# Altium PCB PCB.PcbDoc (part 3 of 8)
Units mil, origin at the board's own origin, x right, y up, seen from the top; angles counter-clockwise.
Board outline 11229.24 x 7764.43 mil, 14 copper layers (Top Layer, GND1, Signal 1, GND2, Signal 2, GND3, Singal 3, Power 1, GND4, Power 2, GND5, Power 3, GND6, Bottom Layer), stack 91.892 mil thick; 877 components, 305 nets, 2660 pads, 2851 vias.
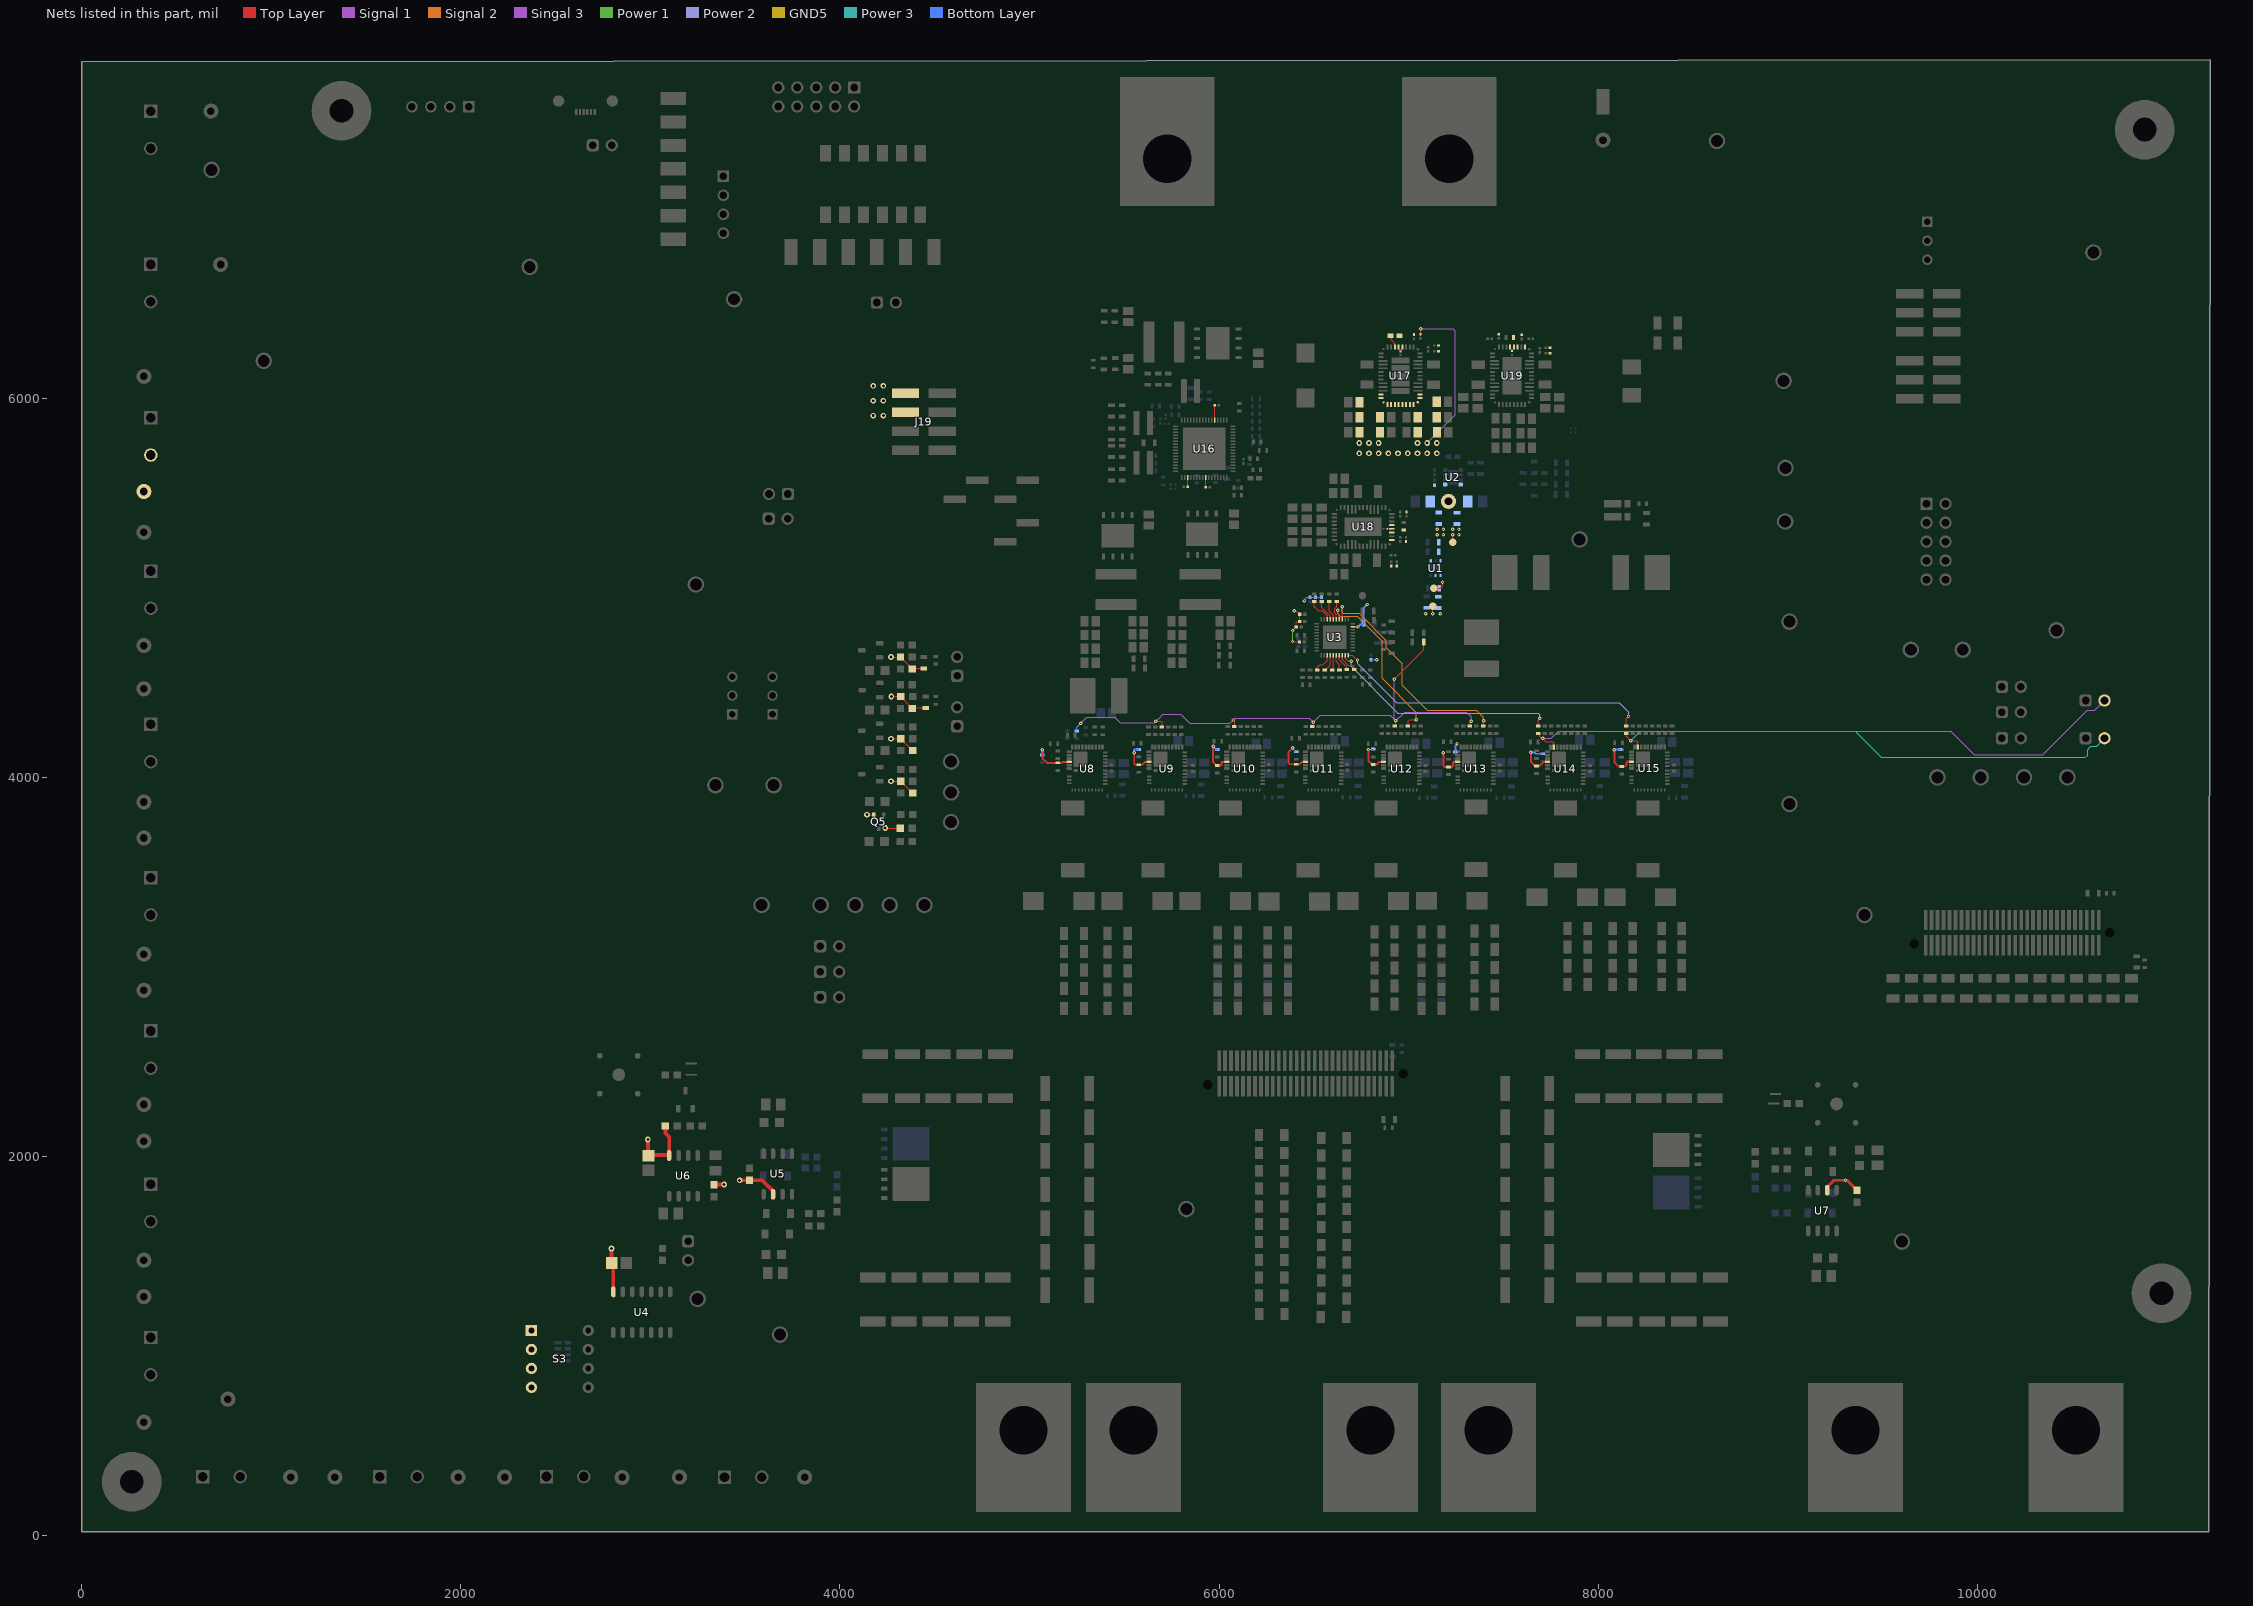
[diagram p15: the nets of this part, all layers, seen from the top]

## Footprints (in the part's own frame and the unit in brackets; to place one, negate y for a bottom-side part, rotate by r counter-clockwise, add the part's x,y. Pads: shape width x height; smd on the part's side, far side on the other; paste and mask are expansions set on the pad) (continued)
Samtec_TSM-103-01-x-DV [mm] "Header, 2.54mm, 3x2, SMT"
  rect 3.68x1.27 smd: 1(-2.475,2.54) 2(2.475,2.54) 3(-2.475,0) 4(2.475,0) 5(-2.475,-2.54) 6(2.475,-2.54)
  silkscreen extent -1.75,-3.81 1.65,3.9, body extent -3.85,-3.81 3.85,3.81, height 9.65
Samtec_TSM-104-01-x-DV [mm] "Header, 2.54mm, 4x2, SMT"
  rect 3.68x1.27 smd: 1(-2.475,3.81) 2(2.475,3.81) 3(-2.475,1.27) 4(2.475,1.27) 5(-2.475,-1.27) 6(2.475,-1.27) 7(-2.475,-3.81) 8(2.475,-3.81)
  silkscreen extent -1.65,-5.08 1.65,5.22, body extent -3.85,-5.08 3.85,5.08, height 9.65
SIL0008D_SMD [mm] "SIP, 8-Leads, Body 2.8x3.0mm, Pitch 0.65mm, Thermal Pad 1.9x1.1mm"
  rrect12% 1.04x0.85 on Bottom Paste: 0(0,-0.525) 0(0,0.525)
  rrect40% 0.6x0.5 smd paste-0.05 mask-0.05: 1(-1.05,0.975) 2(-1.05,0.325) 3(-1.05,-0.325) 4(-1.05,-0.975) 5(1.05,-0.975) 6(1.05,-0.325) 7(1.05,0.325) 8(1.05,0.975)
  rrect17% 1.2x2 smd paste-0.6 mask-0.05: 9(0,0)
  silkscreen extent -1.53,-1.63 1.53,1.63, body extent -1.4,-1.5 1.4,1.5, height 1.53
SLR1050 [mm] "SMD, 2-Leads, Body 10.2x7mm"
  rect 2x3.1 smd: 1(-4.175,0) 2(4.175,0)
  silkscreen extent -4.7,-3.5 4.7,3.5, body extent -4.8,-3.5 4.8,3.5, height 4.95
SOD-123 [mm] "On Semi recommended land pattern"
  rect 0.915x1.22 smd: 1(-1.637,0) 2(1.637,0)
  silkscreen extent -2.74,-1.17 2.03,1.17, body extent -1.93,-0.9 1.93,0.9, height 1.35
SOT-23 [mm] "SOT23, 3-Leads, Body 2.9x1.3mm, Pitch 0.95mm, Lead Span 2.5mm, IPC Medium Density"
  rrect50% 1x0.6 smd: 1(-1.2,0.95) 2(-1.2,-0.95) 3(1.2,0)
  silkscreen extent -1.63,-1.5 0.7,1.5, body extent -1.16,-1.45 1.21,1.45, height 1
SOT-323 [mm] "Diodes Inc recommended land pattern.  2016-02-24"
  rrect21% 0.6x0.47 smd: 1(-0.95,0.65) 2(-0.95,-0.65) 3(0.95,0)
  silkscreen extent -1.14,-1.22 0.78,1.22, body extent -1.13,-1.13 1.12,1.12, height 1.13
SW_78B04ST [mil] "Switch, DIP Slide, 4Pos"
  rect 60x60 hole 31: 1(-150,150)
  round 60 hole 31: 2(-150,50) 3(-150,-50) 4(-150,-150) 5(150,-150) 6(150,-50) 7(150,50) 8(150,150)
  silkscreen extent -174,213 -160,227, body extent -195,-245 195,245, height 337
SW_EG1218 [mm] "TH, 3-Leads, Body 4x11.6mm, Pitch 2.5mm"
  rect 1.4x1.4 hole 0.9: 1(-2.5,0)
  round 1.4 hole 0.9: 2(0,0) 3(2.5,0)
  silkscreen extent -5.8,-2 5.8,2.3, body extent -5.8,-2 5.8,2, height 7.4
SW_SDA06H1SBD [mil] "Swittch SPST 6 Pos."
  rrect7% 59x85 smd: 1(-250,-162) 2(-150,-162) 3(-50,-162) 4(50,-162) 5(150,-162) 6(250,-162) 7(250,162) 8(150,162) 9(50,162) 10(-50,162) 11(-150,162) 12(-250,162)
  body extent -340,-150 340,150, height 197
TC164 [mm] "SMD, 8-Leads, Body 3.2x1.6mm, Pitch 0.8mm"
  rect 0.9x0.45 smd: 1(-0.65,1.2) 2(-0.65,0.4) 3(-0.65,-0.4) 4(-0.65,-1.2) 5(0.65,-1.2) 6(0.65,-0.4) 7(0.65,0.4) 8(0.65,1.2)
  silkscreen extent -1.5,-1.9 1.5,1.9, body extent -0.87,-1.68 0.87,1.68, height 0.71
Testpoint_Keystone_Miniature [mil] "Miniature SMT test point"
  rect 135x70 smd: 1(0,0)
  silkscreen extent -78,-46 78,45, body extent -52,-20 52,20, height 61
TI_Stacked_Overlay_Small [mil]
  silkscreen extent -418,-98 418,98
TP_SM_1MM [mm] "1mm Test Point, SMT"
  round 1 smd paste-0.5: 1(0,0)
TSW-102-07-G-S [mm] "Samtec 100mil, 1x2, 230 mil above insulator"
  rrect50% 1.65x1.65 hole 1.016: 1(-1.27,0)
  round 1.65 hole 1.016: 2(1.27,0)
  silkscreen extent -3.17,-1.27 2.54,1.27, body extent -2.54,-1.27 2.54,1.27, height 8.38
WEEE_Minimum [mil] "WEEElie bin"
  silkscreen extent -95,-172 99,104
Wurth_61000218321 [mm] "Header, 2.54mm, 2x1, SMT"
  rect 1x3 smd: 1(-1.27,1.5) 2(1.27,-1.5)
  silkscreen extent -2.86,-1.27 2.54,1.27, body extent -2.54,-2.5 2.54,2.5, height 6.3
XEL6030_320 [mm] "SMD, 2-Leads, Body 66.36x6.56 mm"
  rrect7% 1.43x5.5 smd: 1(-2.02,0) 2(2.02,0)
  body extent -3.28,-3.38 3.28,3.38, height 3.2

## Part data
C1 C3: library part CMP-0007507-5, "CAP, CERM, 10 uF, 25 V, +/- 20%, X5R, 0603", Cap_Case=0603, Manufacturer="Taiyo Yuden", TempCo=X5R, Tolerance_%=20%, Value1=Unknown, Value2=25V, ValueDisplayed=10uF
C2: library part CMP-0006802-4, "CAP, CERM, 0.1 uF, 50 V, +/- 10%, X7R, 0603", Cap_Case=0603, Manufacturer=AVX, Supplier Part Number 1=478-5052-1-ND, TempCo=X7R, Tolerance_%=10%, Value1=Unknown, Value2=50V, ValueDisplayed=0.1uF
C4: library part CMP-0007007-5, "CAP, CERM, 10 uF, 25 V, +/- 20%, X5R, 0603", Cap_Case=0603, Manufacturer=TDK, Supplier Part Number 1=445-9015-1-ND, TempCo=X5R, Tolerance_%=20%, Value1="0.004639 ohm", Value2=25V, ValueDisplayed=10uF
C5 C6 C299 C307 C317: library part CMP-0008305-2, "CAP, CERM, 22 uF, 25 V, +/- 20%, X5R, 0805", Cap_Case=0805, Manufacturer=MuRata, Supplier Part Number 1=490-10749-1-ND, TempCo=X5R, Tolerance_%=20%, Value1=Unknown, Value2=25V, ValueDisplayed=22uF
C7 C16 C19 C20 C25 C27 C30: library part CMP-0007136-5, "CAP, CERM, 1 uF, 16 V, +/- 10%, X7R, AEC-Q200 Grade 1, 0603", Cap_Case=0603, Manufacturer=MuRata, Supplier Part Number 1=490-5241-6-ND, TempCo=X7R, Tolerance_%=10%, Value1=Unknown, Value2=16V, ValueDisplayed=1uF
C8: library part CMP-0006319-2, "CAP, CERM, 3300 pF, 50 V, +/- 10%, X7R, AEC-Q200 Grade 1, 0402", Cap_Case=0402, Manufacturer=TDK, Supplier Part Number 1=445-6891-1-ND, TempCo=X7R, Tolerance_%=10%, Value1="0.785178 ohm", Value2=50V, ValueDisplayed=3300pF
C9: library part CMP-0006949-5, "CAP, CERM, 4.7 uF, 10 V, +/- 10%, X5R, 0603", Cap_Case=0603, Manufacturer=Kemet, Supplier Part Number 1=399-5503-1-ND, TempCo=X5R, Tolerance_%=10%, Value1="0.006 ohm", Value2=10V, ValueDisplayed=4.7uF
C10 C12: library part CMP-0006233-2, "CAP, CERM, 100 pF, 25 V, +/- 5%, C0G/NP0, 0402", Cap_Case=0402, Manufacturer=Kemet, Supplier Part Number 1=399-1022-1-ND, TempCo=C0G/NP0, Tolerance_%=5%, Value1=Unknown, Value2=25V, ValueDisplayed=100pF
C11 C13 C14 C15: library part CMP-0006439-2, "CAP, CERM, 22 pF, 50 V, +/- 5%, C0G/NP0, 0402", Cap_Case=0402, Manufacturer=MuRata, Supplier Part Number 1=81-GRM1555C1H220JA1D, TempCo=C0G/NP0, Tolerance_%=5%, Value1=Unknown, Value2=50V, ValueDisplayed=22pF
C17 C18: library part CMP-0006235-2, "CAP, CERM, 1000 pF, 50 V, +/- 10%, X7R, 0402", Cap_Case=0402, Manufacturer=Kemet, Supplier Part Number 1=399-1032-1-ND, TempCo=X7R, Tolerance_%=10%, Value1=Unknown, Value2=50V, ValueDisplayed=1000pF
C21 C22: library part CMP-0006663-2, "CAP, CERM, 2200 pF, 25 V, +/- 10%, X7R, 0402", Cap_Case=0402, Manufacturer=MuRata, Supplier Part Number 1=490-5419-1-ND, TempCo=X7R, Tolerance_%=10%, Value1=Unknown, Value2=25V, ValueDisplayed=2200pF
C23 C24: library part CMP-0064970-1, "CAP, CERM, 0.1 uF, 16 V,+/- 10%, X7R, 0201", Cap_Case=0201, Manufacturer=MuRata, Supplier Part Number 1=81-GRM033Z71C104KE4D, TempCo=X7R, Tolerance_%=10%, Value1=Unknown, Value2=16V, ValueDisplayed=0.1uF
C26 C31: library part CMP-0007567-2, "CAP, CERM, 0.1 uF, 25 V, +/- 10%, X7R, 0805", Cap_Case=0805, Manufacturer=AVX, Supplier Part Number 1=478-3755-1-ND, TempCo=X7R, Tolerance_%=10%, Value1="0.28 ohm", Value2=25V, ValueDisplayed=0.1uF
C28 C29: library part CMP-0007542-2, "CAP, CERM, 0.01 uF, 100 V, +/- 5%, X7R, 0805", Cap_Case=0805, Manufacturer=AVX, Supplier Part Number 1=478-3745-1-ND, TempCo=X7R, Tolerance_%=5%, Value1="0.078 ohm", Value2=100V, ValueDisplayed=0.01uF
C32 C33 C34 C35 C36 C37 C38 C39 C40 C41 C42 C43 C44 C45 C46 C47 C48 C49 C50 C51 C52 C53 C54 C55 C56 C57 C58 C59 C60 C61 C62 C63 C64 C65 C66 C67 C68 C69 C70 C71 C72 C73 C74 C75 C76 C77 C78 C79 C80 C81 C89 C90 C91 C92 C93 C94 C95 C96 C97 C98 C99 C100 C101 C102 C103 C104 C105 C106 C107 C108 C109 C110 C111 C112 C113 C114 C115 C116 C117 C118 C119 C120 C121 C122 C123 C124 C125 C126 C127 C128 C129 C130 C131 C132 C133 C134 C135 C136 C137 C138 C139 C140 C141 C142 C143 C144 C145 C146 C147 C148 C149 C150 C151 C152 C153 C154 C155 C156 C157 C158 C159 C160 C161 C162 C163 C164 C165 C166 C167 C168 C169 C170 C173 C174 C175 C176 C189 C190 C191 C192 C205 C206 C207 C208 C221 C222 C223 C224 C237 C238 C239 C240 C253 C254 C255 C256 C269 C270 C271 C272 C285 C286 C287 C288: library part CMP-0008932-2, "CAP, CERM, 220 uF, 4 V, +/- 20%, X5R, 1206_190", Cap_Case=1206, Manufacturer=MuRata, Supplier Part Number 1=490-9774-1-ND, TempCo=X5R, Tolerance_%=20%, Value1=Unknown, Value2=4V, ValueDisplayed=220uF
C82: library part CMP-0006810-4, "CAP, CERM, 0.082 uF, 16 V, +/- 10%, X7R, 0603", Cap_Case=0603, Manufacturer=AVX, Supplier Part Number 1=478-1238-1-ND, TempCo=X7R, Tolerance_%=10%, Value1="0.042 ohm", Value2=16V, ValueDisplayed=0.082uF
C83 C84 C85 C86: library part CMP-0092821-1, "220µF Molded Tantalum Polymer Capacitor 25V 2924 (7361 Metric) 100mOhm @ 100kHz", Digikey Part Number=478-12518-1-ND, Leakage Current=550uA, Manufacturer=AVX, Mouser Part Number=581-TCN4227M025R0100, Operating Temperature Range="-55°C to +105°C", Tolerance_%=20%, ValueDisplayed=220uF
C87 C88: library part CMP-0008667-2, "CAP, CERM, 22 uF, 35 V, +/- 20%, X5R, 1206", Cap_Case=1206_180, Manufacturer=TDK, Supplier Part Number 1=445-8045-1-ND, TempCo=X5R, Tolerance_%=20%, Value1="0.002398 ohm", Value2=35V, ValueDisplayed=22uF
C171 C187 C203 C219 C235 C251 C267 C283: library part CMP-0006673-2, "CAP, CERM, 1000 pF, 50 V, +/- 10%, X7R, 0402", Cap_Case=0402, Manufacturer=MuRata, Supplier Part Number 1=490-1303-1-ND, TempCo=X7R, Tolerance_%=10%, Value1=Unknown, Value2=50V, ValueDisplayed=1000pF
C172 C177 C188 C193 C204 C209 C220 C225 C236 C241 C252 C257 C268 C273 C284 C289: library part CMP-0012242-3, "CAP, Aluminum Polymer, 470 uF, 2.5 V, +/- 20%, 0.003 ohm, SMD_7.3x1.9x4.3mm SMD", Manufacturer=Panasonic, Supplier Part Number 1=95W5408, Tolerance_%=20%, Value1="0.003 ohm", Value2=2.5V, ValueDisplayed=470uF
C178 C194 C210 C226 C242 C258 C274 C290: library part CMP-0086485-1, "CAP CER 1UF 25V X6S 0402", Manufacturer=Murata, TempCo=22%, Tolerance_%=10%
C179 C180 C181 C195 C196 C197 C211 C212 C213 C227 C228 C229 C243 C244 C245 C259 C260 C261 C275 C276 C277 C291 C292 C293: library part CMP-0008293-2, "CAP, CERM, 22 uF, 16 V, +/- 20%, X5R, 0805", Cap_Case=0805, Manufacturer=MuRata, PartNumber=GRM21BR61C226ME44, TempCo=X5R, Tolerance_%=20%, Value1=Unknown, Value2=16V, ValueDisplayed=22uF
C182 C186 C199 C202 C216 C218 C230 C234 C248 C250 C264 C266 C278 C282 C295 C298: library part CMP-0006356-2, "CAP, CERM, 0.1 uF, 50 V, +/- 10%, X7R, AEC-Q200 Grade 1, 0402", Cap_Case=0402, Manufacturer=MuRata, Supplier Part Number 1=490-10672-1-ND, TempCo=X7R, Tolerance_%=10%, Value1=Unknown, Value2=50V, ValueDisplayed=0.1uF
C183 C184 C198 C200 C214 C215 C231 C232 C246 C247 C262 C263 C280 C281 C294 C296: library part CMP-0006263-2, "CAP, CERM, 2.2 uF, 10 V, +/- 10%, X5R, 0402", Cap_Case=0402, Manufacturer=TDK, PartNumber=C1005X5R1A225K050BC, Supplier Part Number 1=445-7392-1-ND, TempCo=X5R, Tolerance_%=10%, Value1=Unknown, Value2=10V, ValueDisplayed=2.2uF
C185 C201 C217 C233 C249 C265 C279 C297: library part CMP-0006233-2, "CAP, CERM, 100 pF, 25 V, +/- 5%, C0G/NP0, 0402", Cap_Case=0402, Manufacturer=Kemet, PartNumber=C0402C101J3GACTU, Supplier Part Number 1=399-1022-1-ND, TempCo=C0G/NP0, Tolerance_%=5%, Value1=Unknown, Value2=25V, ValueDisplayed=100pF
C300 C308 C318 C346 C347 C352: library part CMP-0009719-2, "CAP, CERM, 0.1 uF, 25 V, +/- 10%, X5R, 0201", Cap_Case=0201, Manufacturer=MuRata, Supplier Part Number 1=GRM033R61E104KE14D-ND, TempCo=X5R, Tolerance_%=10%, Value1=Unknown, Value2=25V, ValueDisplayed=0.1uF
C301 C302 C303 C306 C309 C310 C311 C312 C313 C316 C359 C360 C361 C362 C363 C364 C365 C366 C367 C368 C372 C373 C374 C375 C376 C377 C378 C379 C380 C381 C385 C386 C387 C388 C390 C391 C392 C393 C394 C395 C398 C399 C400: library part CMP-0008280-2, "CAP, CERM, 100 uF, 6.3 V, +/- 20%, X5R, 0805", Cap_Case=0805, Manufacturer=MuRata, TempCo=X5R, Tolerance_%=20%, Value1=Unknown, Value2=6.3V, ValueDisplayed=100uF
C304 C305 C314 C319 C322 C323 C324 C326 C327 C328 C331 C332 C333 C334 C335 C396: library part CMP-0007324-5, "CAP, CERM, 22 uF, 10 V, +/- 20%, X5R, 0603", Cap_Case=0603, Manufacturer=MuRata, Supplier Part Number 1=490-10476-1-ND, TempCo=X5R, Tolerance_%=20%, Value1=Unknown, Value2=10V, ValueDisplayed=22uF
C315 C330 C339 C340 C341 C401: library part CMP-0086193-1, "CAP, CERM, 10 µF, 10 V,+/- 10%, X5R, 0603", Cap_Case=0603, Manufacturer=MuRata, TempCo=X5R, Tolerance_%=10%, Value2=10V, ValueDisplayed=10µF
C320 C321: library part CMP-0078699-1, "CAP, CERM, 47 µF, 10 V,+/- 20%, X5R, 0805", Cap_Case=0805, Manufacturer=MuRata, Supplier Part Number 1=490-9961-1-ND, TempCo=X5R, Tolerance_%=20%, Value2=10V, ValueDisplayed=47µF
C325: library part CMP-0006581-2, "CAP, CERM, 4.7 uF, 10 V, +/- 20%, X5R, 0402", Cap_Case=0402, Manufacturer=MuRata, TempCo=X5R, Tolerance_%=20%, Value1=Unknown, Value2=10V, ValueDisplayed=4.7uF
C329: library part CMP-0007313-5, "CAP, CERM, 47 uF, 6.3 V, +/- 20%, X5R, 0603", Cap_Case=0603, Manufacturer=MuRata, TempCo=X5R, Tolerance_%=20%, Value1=Unknown, Value2=6.3V, ValueDisplayed=47uF
C336: library part CMP-0011853-2, "CAP, TA, 47 uF, 35 V, +/- 20%, 0.9 ohm, AEC-Q200 Grade 1, SMD", Cap_Case=7343-43, Manufacturer=AVX, Supplier Part Number 1=478-3958-1-ND, Tolerance_%=20%, Value1="0.9 ohm", Value2=35V, ValueDisplayed=47uF
C337 C338: library part CMP-0006543-2, "CAP, CERM, 2.2 uF, 6.3 V, +/- 10%, X5R, 0402", Cap_Case=0402, Manufacturer=MuRata, Supplier Part Number 1=81-GRM155R60J225KE5D, TempCo=X5R, Tolerance_%=10%, Value1=Unknown, Value2=6.3V, ValueDisplayed=2.2uF
C342: library part CMP-0006268-1, "CAP, CERM, 4.7 uF, 10 V, +/- 10%, X5R, 0402", Cap_Case=0402_065, Manufacturer=TDK, Supplier Part Number 1=445-13820-1-ND, TempCo=X5R, Tolerance_%=10%, Value1="0.003417 ohm", Value2=10V, ValueDisplayed=4.7uF
C343 C344: library part CMP-0064909-1, "CAP, CERM, 1 uF, 10 V,+/- 20%, X5R, 0201", Cap_Case=0201, Manufacturer=MuRata, Supplier Part Number 1=490-13226-1-ND, TempCo=X5R, Tolerance_%=20%, Value1=Unknown, Value2=10V, ValueDisplayed=1uF
C345 C397: library part CMP-0006545-1, "CAP, CERM, 22 uF, 6.3 V, +/- 20%, X5R, 0402", Cap_Case=0402, Manufacturer=MuRata, TempCo=X5R, Tolerance_%=20%, Value1=Unknown, Value2=6.3V, ValueDisplayed=22uF
C348 C349: library part CMP-0006620-2, "CAP, CERM, 1 uF, 35 V, +/- 20%, X5R, 0402", Cap_Case=0402, Manufacturer=MuRata, Supplier Part Number 1=490-10020-1-ND, TempCo=X5R, Tolerance_%=20%, Value1=Unknown, Value2=35V, ValueDisplayed=1uF
C350 C351: library part CMP-0006269-2, "CAP, CERM, 4.7 uF, 10 V, +/- 20%, X5R, 0402", Cap_Case=0402, Manufacturer=TDK, Supplier Part Number 1=445-8023-1-ND, TempCo=X5R, Tolerance_%=20%, Value1=Unknown, Value2=10V, ValueDisplayed=4.7uF
C353 C354 C355: library part CMP-0006553-3, "CAP, CERM, 4.7 uF, 6.3 V, +/- 20%, X5R, 0402", Cap_Case=0402, Manufacturer=MuRata, Supplier Part Number 1=490-5408-1-ND, TempCo=X5R, Tolerance_%=20%, Value1="0.009 ohm", Value2=6.3V, ValueDisplayed=4.7uF
C356: library part CMP-0086192-1, "CAP, CERM, 0.1 µF, 16 V,+/- 10%, X5R, 0201", Cap_Case=0201, Manufacturer=MuRata, TempCo=X5R, Tolerance_%=10%, Value2=16V, ValueDisplayed=0.1µF
C357 C358: library part CMP-0008656-2, "CAP, CERM, 47 uF, 25 V, +/- 20%, X5R, 1206_190", Cap_Case=1206, Manufacturer=TDK, PartNumber=C3216X5R1E476M160AC, Supplier Part Number 1=445-8047-1-ND, TempCo=X5R, Tolerance_%=20%, Value1=Unknown, Value2=25V, ValueDisplayed=47uF
C369 C382 C389: library part CMP-0006612-2, "CAP, CERM, 4.7 uF, 25 V, +/- 20%, X5R, 0402", Cap_Case=0402, Manufacturer=MuRata, TempCo=X5R, Tolerance_%=20%, Value1=Unknown, Value2=25V, ValueDisplayed=4.7uF
C370 C371 C383 C384: library part CMP-0008646-2, "CAP, CERM, 47 uF, 25 V, +/- 20%, JB, 1206", Cap_Case=1206, Manufacturer=TDK, Supplier Part Number 1=445-11717-1-ND, TempCo=JB, Tolerance_%=20%, Value1=Unknown, Value2=25V, ValueDisplayed=47uF
D1 D2 D4 D5 D8 D9 D11 D12: library part CMP-0028525-2, "Diode, Schottky, 30 V, 0.5 A, SOD-123", Manufacturer="ON Semiconductor", Value1=0.5A, Value2=0.43V
D3 D6 D10 D13 D18: library part CMP-0002829-3, "LED, Red, SMD", Color=red, Manufacturer=Lite-On, Value1=W, Value2=2V
D7: library part CMP-0028451-2, "Diode, Schottky, 30 V, 0.2 A, SOT-23", Manufacturer="Diodes Inc.", Value1=0.2A, Value2=0.65V
D14 D15 D16 D17: library part CMP-0002888-2, "LED, Green, SMD", Color=Green, Manufacturer=Lite-On, Value1=W, Value2=2V
H1 H3 H5 H7: library part CMP-0003617-1, "Machine Screw, Round, #4-40 x 1/4, Nylon, Philips panhead", Manufacturer="B&F Fastener Supply", Supplier Part Number 1=H542-ND
H2 H4 H6 H8: library part CMP-0003610-1, "Standoff, Hex, 0.5\"L #4-40 Nylon", Manufacturer=Keystone, Supplier Part Number 1=36-1902C-ND
J1 J4: library part CMP-0055331-1, "Header, 2.54mm, 4x1, Tin, TH", Color=Black, Current_A=4A, Manufacturer=Molex, Supplier Part Number 1=WM50016-04-ND, Voltage_V=250V
J2 J3 J5 J6 J8 J24 J29 J32 J38 J39 J40 J41 J42 J43 J44: library part CMP-0075405-3, "Header, 100mil, 2x1, Gold, TH", Color=Black, Current_A=6.3A, Manufacturer=Samtec, Supplier Part Number 1=SAM1029-02-ND, Voltage_V=550V
J7: library part CMP-0054834-2, "Header (shrouded), 100mil, 5x2, Gold, TH", Manufacturer="TE Connectivity", Supplier Part Number 1=A33159-ND
J9 J10: library part CMP-0003859-2, "C2000 controlCARD-180HSEC (60-pin addon) connector, SMT", Manufacturer=Samtec
J11 J12: library part CMP-0075154-1, "Connector, SMT, SMB Jack Assembly 50 ohm", Manufacturer="Cinch Connectivity", Supplier Part Number 1=J816-ND
J13 J14 J15 J16 J17 J18 J30 J31 J33 J34 J35 J36 J37: library part CMP-0055506-1, "Terminal Block, 2x1, 5mm, Green, TH", Color=Green, Manufacturer="Phoenix Contact", Supplier Part Number 1=277-6405-ND
J19: library part CMP-0075593-2, "Header, 2.54mm, 4x2, Gold, SMT", Color=Black, Current_A=4.9A, Manufacturer=Samtec, Supplier Part Number 1=TSM-104-01-L-DV-ND, Voltage_V=475V
J20 J21 J22: library part CMP-0054787-1, "Header, 2.54mm, 2x1, Gold, SMT", Color=Black, Manufacturer="Wurth Elektronik"
J23: library part CMP-0055367-1, "FFC/FPC Connector, 6 POS, 0.5mm, R/A, Tin, SMT", Color=withe,black, Current_A=5dA, Manufacturer=Molex, Supplier Part Number 1=WM11020CT-ND, Voltage_V=50V
J25 J27: library part CMP-0075648-2, "Header, 2.54mm, 3x2, Gold, SMT", Color=Black, Current_A=4.9A, Manufacturer=Samtec, Supplier Part Number 1=TSM-103-01-L-DV-ND, Voltage_V=475V
J26: "Header (shrouded), 100mil, 5x2, High-Temperature, Gold, TH", Manufacturer=3M, PartNumber=N2510-6002-RB, Supplier Part Number 1=MHC10K-ND
J28: library part CMP-0075048-1, "Header, 2.54mm, 3x1, Gold, TH", Manufacturer="Fischer Elektronik"
L1: library part CMP-0092884-1, "Fixed Ind 55NH 35A 0.2 Mohm SMD", Digikey Part Number=553-PA4059.550HLTCT-ND, Manufacturer=Pulse, Mouser Part Number=673-PA4059.550HLT, Operating Temperature Range="-40°C to +125°C", Test Frequency=100kHz, Tolerance_%=20%
L2 L3 L4 L5 L6 L7 L8 L9: library part CMP-0060908-1, "Inductor, Shielded, Ferrite, 150 nH, 51 A, 0.0004 ohm, SMD", Manufacturer=Coilcraft, Supplier Part Number 1=994-SLR1050A-151KEB, Value1="0.0004 ohm", Value2=51A, ValueDisplayed=150nH
L10 L11 L12: library part CMP-0061103-3, "Inductor, Shielded, Composite, 470 nH, 22.3 A, 0.00331 ohm, AEC-Q200 Grade 1, SMD", Manufacturer=Coilcraft, Value1="0.00331 ohm", Value2=22.3A, ValueDisplayed=470nH
L13 L14 L15: library part CMP-0087112-1, "Shielded Power Inductors", Manufacturer=Coilcraft
Logo1: library part CMP-0074844-1
Logo2: library part CMP-0074838-1, "Texas Instrument Corporate Signature"
Logo3: library part CMP-0074847-1, "FCC_disclaimer"
Logo4: library part CMP-0074769-1
NT1 NT2 NT3 NT4 NT5 NT6 NT7 NT8 NT9 NT10 NT11 NT12 NT13 NT14 NT15 NT16 NT17 NT18 NT19: library part CMP-0078142-4, "Single point connection between nets.", Manufacturer=N/A
Q1 Q2 Q3 Q4: library part CMP-0000556-1, "MOSFET, N-CH, 30 V, 100 A, DQH0008A (VSON-CLIP-8)", Alternate Manufacturer=None, Manufacturer="Texas Instruments", Supplier Part Number 1=296-27232-1-ND, Value1=0, Value2="18 nC"
Q5: library part CMP-0000010-3, "MOSFET, P-CH, -20 V, -0.39 A, SOT-323", Alternate Manufacturer=None, Manufacturer="Infineon Technologies", Value1=1
Q6 Q7 Q8 Q9: library part CMP-0000947-2, "MOSFET, N-CH, 100 V, 0.17 A, SOT-23", Alternate Manufacturer=None, Manufacturer="Fairchild Semiconductor", Supplier Part Number 1=BSS123NCT-ND, Value1=1, Value2="1.8 nC"
Q10 Q11 Q12: library part CMP-0000278-2, "MOSFET, 2-CH, N-CH, 25 V, 50 A, DQY0008A (LSON-CLIP-8)", Alternate Manufacturer=None, Manufacturer="Texas Instruments", Supplier Part Number 1=296-35026-1-ND, Value1=0.004, Value2="9.7 nC"
R1 R2 R5: library part CMP-0022900-4, "RES, 1.00, 1%, 0.1 W, 0603", Manufacturer=Yageo, Power_W=100mW, Supplier Part Number 1=311-1.00HRCT-ND, TempCo="200 ppm/C", Tolerance_%=1%, Value2=0.1W, Value_Code=1R00, ValueDisplayed=1.00
R3: library part CMP-0027760-1, "RES, 523 k, 1%, 0.05 W, 0201", Manufacturer="Yageo America", Power_W=50mW, Supplier Part Number 1=YAG2716CT-ND, TempCo="200 ppm/C", Tolerance_%=1%, Value2=0.05W, Value_Code=523k
R4 R8 R10 R15 R16 R17 R24 R25 R26 R27 R28 R29 R38 R139 R140 R141 R142 R143 R145 R146: library part CMP-0025697-4, "RES, 0, 5%, 0.1 W, AEC-Q200 Grade 0, 0603", Manufacturer=Vishay-Dale, Power_W=100mW, Supplier Part Number 1=541-0.0GCT-ND, TempCo="200 ppm/C", Tolerance_%=5%, Value2=0.1W, Value_Code=0000, ValueDisplayed=0
R6: library part CMP-0027261-3, "RES, 100 k, 1%, 0.05 W, 0201", Manufacturer=Vishay-Dale, Power_W=50mW, Supplier Part Number 1=541-100KAABCT-ND, TempCo="100 ppm/C", Tolerance_%=1%, Value2=0.05W, Value_Code=100k
R7 R9 R11 R12 R20 R21 R148 R150 R151 R153 R154 R156 R158 R160 R161 R162 R164 R166 R168 R169 R170 R172 R174 R175 R177 R178 R180 R182 R184 R185 R186 R188 R190 R192 R193 R194 R196 R198 R199 R201 R202 R204 R206 R208 R209 R210 R214: library part CMP-0026822-3, "RES, 0, 5%, 0.063 W, AEC-Q200 Grade 0, 0402", Manufacturer=Vishay-Dale, Power_W=63mW, Supplier Part Number 1=541-0.0JCT-ND, TempCo="200 ppm/C", Tolerance_%=5%, Value2=0.063W, Value_Code=0000, ValueDisplayed=0
R13: library part CMP-0022204-4, "RES, 20.0 k, 1%, 0.1 W, AEC-Q200 Grade 0, 0603", Manufacturer=Vishay-Dale, Power_W=100mW, Supplier Part Number 1=541-20.0KHCT-ND, TempCo="100 ppm/C", Tolerance_%=1%, Value2=0.1W, Value_Code=20k0, ValueDisplayed=20.0k
R14: library part CMP-0022150-4, "RES, 1.30 M, 1%, 0.1 W, AEC-Q200 Grade 0, 0603", Manufacturer=Vishay-Dale, Power_W=100mW, Supplier Part Number 1=541-1.30MHCT-ND, TempCo="100 ppm/C", Tolerance_%=1%, Value2=0.1W, Value_Code=1M30, ValueDisplayed=1.30M
R18: library part CMP-0026461-2, "RES, 59.0 k, 1%, 0.063 W, AEC-Q200 Grade 0, 0402", Manufacturer=Vishay-Dale, Power_W=63mW, Supplier Part Number 1=541-59.0KLCT-ND, TempCo="100 ppm/C", Tolerance_%=1%, Value2=0.063W, Value_Code=59k0, ValueDisplayed=59.0k
R19: library part CMP-0026875-3, "RES, 20 k, 5%, 0.063 W, AEC-Q200 Grade 0, 0402", Manufacturer=Vishay-Dale, Power_W=63mW, Supplier Part Number 1=541-20KJCT-ND, TempCo="200 ppm/C", Tolerance_%=5%, Value2=0.063W, Value_Code=20k0, ValueDisplayed=20k
R22 R23: library part CMP-0025729-4, "RES, 1.0 k, 5%, 0.1 W, AEC-Q200 Grade 0, 0603", Manufacturer=Vishay-Dale, Power_W=100mW, Supplier Part Number 1=541-1.0KGCT-ND, TempCo="200 ppm/C", Tolerance_%=5%, Value2=0.1W, Value_Code=1k00, ValueDisplayed=1.0k
R30 R31 R32 R34 R35 R36: library part CMP-0027186-1, "RES, 10 k, 5%, 0.05 W, 0201", Manufacturer="Yageo America", Power_W=50mW, Supplier Part Number 1=603-RC0201JR-7D10KL, TempCo="200 ppm/C", Tolerance_%=5%, Value2=0.05W, Value_Code=10k0, ValueDisplayed=10k
R33 R37: library part CMP-0022024-4, "RES, 121 k, 1%, 0.1 W, AEC-Q200 Grade 0, 0603", Manufacturer=Vishay-Dale, Power_W=100mW, Supplier Part Number 1=541-121KHCT-ND, TempCo="100 ppm/C", Tolerance_%=1%, Value2=0.1W, Value_Code=121k
R39 R40 R41 R42 R44 R45 R46 R47 R48 R49 R50 R51 R52 R53 R54 R55 R56 R57 R58 R59 R60 R61 R62 R63 R64 R65 R66 R67 R68 R69 R70 R71 R72 R73 R82 R83 R86 R87 R88 R89 R90 R91 R92 R93 R94 R95 R96 R97 R98 R99 R100 R101 R102 R103 R104 R105 R106 R107 R108 R109 R110 R111 R112 R113 R114 R115 R125 R126: library part CMP-0015782-2, "RES, 0.2, 1%, 2 W, 2512", Manufacturer="Stackpole Electronics Inc", Power_W=2W, Supplier Part Number 1=CSRN2512FKR200CT-ND, TempCo="200 ppm/C", Tolerance_%=1%, Value_Code=R200, ValueDisplayed=0.2
R43: library part CMP-0015378-3, "RES, 10 k, 5%, 0.0625 W, 3.2x1.6mm", Manufacturer="Yageo America", Power_W=62.5mW, Supplier Part Number 1=TC164J-10KCT-ND, TempCo="200 ppm/C", Tolerance_%=5%, Value2=0.0625W, Value_Code=10k0, ValueDisplayed=10k
R74 R75 R118 R119: library part CMP-0022590-4, "RES, 75.0, 1%, 0.1 W, AEC-Q200 Grade 0, 0603", Manufacturer=Vishay-Dale, Power_W=100mW, Supplier Part Number 1=541-75.0HCT-ND, TempCo="100 ppm/C", Tolerance_%=1%, Value2=0.1W, Value_Code=75R0, ValueDisplayed=75.0
R76 R81 R120 R127: library part CMP-0020527-3, "RES, 330, 5%, 0.125 W, AEC-Q200 Grade 0, 0805", Manufacturer=Vishay-Dale, Power_W=125mW, Supplier Part Number 1=541-330ACT-ND, TempCo="200 ppm/C", Tolerance_%=5%, Value2=0.125W, Value_Code=330R, ValueDisplayed=330
R77 R78 R121 R122: library part CMP-0021991-4, "RES, 100, 1%, 0.1 W, AEC-Q200 Grade 0, 0603", Manufacturer=Vishay-Dale, Power_W=100mW, Supplier Part Number 1=541-100HCT-ND, TempCo="100 ppm/C", Tolerance_%=1%, Value2=0.1W, Value_Code=100R, ValueDisplayed=100
R79 R80 R85 R123 R124 R133 R135 R136 R137 R138: library part CMP-0025701-4, "RES, 10 k, 5%, 0.1 W, AEC-Q200 Grade 0, 0603", Manufacturer=Vishay-Dale, Power_W=100mW, Supplier Part Number 1=541-10KGCT-ND, TempCo="200 ppm/C", Tolerance_%=5%, Value2=0.1W, Value_Code=10k0, ValueDisplayed=10k
R84 R116: library part CMP-0022634-4, "RES, 8.06 k, 1%, 0.1 W, AEC-Q200 Grade 0, 0603", Manufacturer=Vishay-Dale, Power_W=100mW, Supplier Part Number 1=541-8.06KHCT-ND, TempCo="100 ppm/C", Tolerance_%=1%, Value2=0.1W, Value_Code=8k06, ValueDisplayed=8.06k
R117: library part CMP-0021990-4, "RES, 100 k, 1%, 0.1 W, AEC-Q200 Grade 0, 0603", Manufacturer=Vishay-Dale, Power_W=100mW, Supplier Part Number 1=541-100KHCT-ND, TempCo="100 ppm/C", Tolerance_%=1%, Value2=0.1W, Value_Code=100k
R128: library part CMP-0025963-3, "RES, 10.0, 1%, 0.063 W, AEC-Q200 Grade 0, 0402", Manufacturer=Vishay-Dale, Power_W=63mW, Supplier Part Number 1=541-10.0LCT-ND, TempCo="100 ppm/C", Tolerance_%=1%, Value2=0.063W, Value_Code=10R0, ValueDisplayed=10.0
R129: library part CMP-0015255-1, "RES, 0.0005, 1%, 1 W, 1.5x3.15mm", Manufacturer=Cyntec, Power_W=1W, TempCo="700 ppm/C", Tolerance_%=1%, Value_Code=L5000, ValueDisplayed=0.0005
R130 R131 R132 R134 R144: library part CMP-0025726-4, "RES, 180, 5%, 0.1 W, AEC-Q200 Grade 0, 0603", Manufacturer=Vishay-Dale, Power_W=100mW, Supplier Part Number 1=541-180GCT-ND, TempCo="200 ppm/C", Tolerance_%=5%, Value2=0.1W, Value_Code=180R, ValueDisplayed=180
R147 R155 R163 R171 R179 R187 R195 R203: library part CMP-0025743-4, "RES, 1.0, 5%, 0.1 W, AEC-Q200 Grade 0, 0603", Manufacturer=Vishay-Dale, Power_W=100mW, Supplier Part Number 1=541-1.0GCT-ND, TempCo="200 ppm/C", Tolerance_%=5%, Value2=0.1W, Value_Code=1R00, ValueDisplayed=1.0
R149 R157 R165 R173 R181 R189 R197 R205: library part CMP-0085489-1, "RES, 10.2 k, 0.1%, 0.063 W, AEC-Q200 Grade 1, 0402", Manufacturer=Panasonic, Power_W=63mW, TempCo="25 ppm/C", Tolerance_%=0.1%, Value2=0.063W, Value_Code=10k2, ValueDisplayed=10.2k
R152 R159 R167 R176 R183 R191 R200 R207: library part CMP-0026898-3, "RES, 2.2, 5%, 0.063 W, AEC-Q200 Grade 0, 0402", Manufacturer=Vishay-Dale, Power_W=63mW, Supplier Part Number 1=541-2.2JCT-ND, TempCo="200 ppm/C", Tolerance_%=5%, Value2=0.063W, Value_Code=2R20, ValueDisplayed=2.2
R211 R212 R213: library part CMP-0025992-3, "RES, 12.4 k, 1%, 0.063 W, AEC-Q200 Grade 0, 0402", Manufacturer=Vishay-Dale, Power_W=63mW, Supplier Part Number 1=541-12.4KLCT-ND, TempCo="100 ppm/C", Tolerance_%=1%, Value2=0.063W, Value_Code=12k4, ValueDisplayed=12.4k
R215 R216 R217 R218 R219 R220 R221 R222 R223 R224 R225: library part CMP-0026823-3, "RES, 100 k, 5%, 0.063 W, AEC-Q200 Grade 0, 0402", Manufacturer=Vishay-Dale, Power_W=63mW, Supplier Part Number 1=541-100KJCT-ND, TempCo="200 ppm/C", Tolerance_%=5%, Value2=0.063W, Value_Code=100k
R226 R227: library part CMP-0026852-3, "RES, 1.0 k, 5%, 0.063 W, AEC-Q200 Grade 0, 0402", Manufacturer=Vishay-Dale, Power_W=63mW, Supplier Part Number 1=541-1.0KJCT-ND, TempCo="200 ppm/C", Tolerance_%=5%, Value2=0.063W, Value_Code=1k00, ValueDisplayed=1.0k
R228: library part CMP-0027922-1, "RES, 91.0 k, 1%, 0.05 W, 0201", Manufacturer="Yageo America", Power_W=50mW, Supplier Part Number 1=YAG2842CT-ND, TempCo="200 ppm/C", Tolerance_%=1%, Value2=0.05W, Value_Code=91k0, ValueDisplayed=91.0k
R229: library part CMP-0027301-2, "RES, 10.2 k, 1%, 0.05 W, 0201", Manufacturer="Yageo America", Power_W=50mW, Supplier Part Number 1=311-10.2KMCT-ND, TempCo="200 ppm/C", Tolerance_%=1%, Value2=0.05W, Value_Code=10k2, ValueDisplayed=10.2k
R230 R235 R242: library part CMP-0027945-1, "RES, 10.0 k, 1%, 0.05 W, 0201", Manufacturer="Yageo America", Power_W=50mW, Supplier Part Number 1=603-RC0201FR-7D10KL, TempCo="200 ppm/C", Tolerance_%=1%, Value2=0.05W, Value_Code=10k0, ValueDisplayed=10.0k
R231: library part CMP-0027303-2, "RES, 10.7 k, 1%, 0.05 W, 0201", Manufacturer="Yageo America", Power_W=50mW, Supplier Part Number 1=311-10.7KMCT-ND, TempCo="200 ppm/C", Tolerance_%=1%, Value2=0.05W, Value_Code=10k7, ValueDisplayed=10.7k
R232: library part CMP-0027766-1, "RES, 53.6 k, 1%, 0.05 W, 0201", Manufacturer="Yageo America", Power_W=50mW, Supplier Part Number 1=YAG2722CT-ND, TempCo="200 ppm/C", Tolerance_%=1%, Value2=0.05W, Value_Code=53k6, ValueDisplayed=53.6k
R233: library part CMP-0027281-3, "RES, 56.0 k, 1%, 0.05 W, 0201", Manufacturer=Vishay-Dale, Power_W=50mW, Supplier Part Number 1=541-56.0KAABCT-ND, TempCo="100 ppm/C", Tolerance_%=1%, Value2=0.05W, Value_Code=56k0, ValueDisplayed=56.0k
R234 R239 R241 R246: library part CMP-0027262-3, "RES, 10.0 k, 1%, 0.05 W, 0201", Manufacturer=Vishay-Dale, Power_W=50mW, Supplier Part Number 1=541-10.0KAABCT-ND, TempCo="100 ppm/C", Tolerance_%=1%, Value2=0.05W, Value_Code=10k0, ValueDisplayed=10.0k
R236: library part CMP-0027284-3, "RES, 9.09 k, 1%, 0.05 W, 0201", Manufacturer=Vishay-Dale, Power_W=50mW, Supplier Part Number 1=541-9.09KAABCT-ND, TempCo="100 ppm/C", Tolerance_%=1%, Value2=0.05W, Value_Code=9k09, ValueDisplayed=9.09k
R237 R244: library part CMP-0027372-2, "RES, 15.4 k, 1%, 0.05 W, 0201", Manufacturer="Yageo America", Power_W=50mW, Supplier Part Number 1=YAG2421CT-ND, TempCo="200 ppm/C", Tolerance_%=1%, Value2=0.05W, Value_Code=15k4, ValueDisplayed=15.4k
R238 R245: library part CMP-0027398-2, "RES, 17.4 k, 1%, 0.05 W, 0201", Manufacturer="Yageo America", Power_W=50mW, Supplier Part Number 1=YAG2445CT-ND, TempCo="200 ppm/C", Tolerance_%=1%, Value2=0.05W, Value_Code=17k4, ValueDisplayed=17.4k
R240: library part CMP-0027529-1, "RES, 26.1 k, 1%, 0.05 W, 0201", Manufacturer="Yageo America", Power_W=50mW, Supplier Part Number 1=YAG2544CT-ND, TempCo="200 ppm/C", Tolerance_%=1%, Value2=0.05W, Value_Code=26k1, ValueDisplayed=26.1k
R243: library part CMP-0027362-2, "RES, 14.0 k, 1%, 0.05 W, 0201", Manufacturer="Yageo America", Power_W=50mW, Supplier Part Number 1=YAG2413CT-ND, TempCo="200 ppm/C", Tolerance_%=1%, Value2=0.05W, Value_Code=14k0, ValueDisplayed=14.0k
S1 S2: library part CMP-0002206-2, "Switch, SPDT, Slide, On-On, 2 Pos, TH", CurrentRating_mA=200A, Manufacturer=E-Switch, Supplier Part Number 1=EG1903-ND
S3: library part CMP-0002130-2, "DIP Switch, SPST 4Pos, Slide, TH", CurrentRating_mA=150A, Manufacturer=Grayhill, Supplier Part Number 1=GH7184-ND
S4: library part CMP-0002114-3, "Switch, SPST 6Pos, SMT", CurrentRating_mA=25A, Manufacturer="C&K Components", Supplier Part Number 1=CKN6080-ND
T1 T2 T3 T4 T5 T6 T7 T8: library part CMP-0055443-2, "Terminal 90A Lug", Manufacturer=Panduit, Supplier Part Number 1=CB70-14-CY-ND, Voltage_V=600V
TP1 TP4 TP47 TP49 TP51 TP53 TP55 TP57 TP60 TP67 TP69 TP71 TP74 TP80 TP82: library part CMP-0055137-1, "Test Point, Miniature, Red, TH", Color=Red, Manufacturer=Keystone, Supplier Part Number 1=36-5000-ND
TP2 TP3 TP6 TP8: library part CMP-0003825-1, "1mm Test Point, SMT", Manufacturer=Any
TP5 TP48 TP50 TP52 TP54 TP56 TP58 TP68 TP77 TP81 TP83: library part CMP-0055138-1, "Test Point, Miniature, Black, TH", Color=Black, Manufacturer=Keystone, Supplier Part Number 1=36-5001-ND
TP7 TP17 TP18 TP21 TP22 TP23 TP24 TP25 TP26 TP27 TP84 TP85 TP86 TP87: library part CMP-0055143-1, "Test Point, Compact, Black, TH", Color=Black, Manufacturer=Keystone, PartNumber=5006, Supplier Part Number 1=36-5006-ND
TP9 TP10 TP11 TP12 TP13 TP14 TP28 TP29 TP30 TP31 TP33 TP35 TP37 TP39 TP41 TP43 TP45: library part CMP-0055144-1, "Test Point, Compact, White, TH", Color=White, Manufacturer=Keystone, PartNumber=5007, Supplier Part Number 1=36-5007-ND
TP15: library part CMP-0055144-1, "Test Point, Compact, White, TH", Color=White, Manufacturer=Keystone, Supplier Part Number 1=36-5007-ND
TP16 TP19 TP20: library part CMP-0055142-1, "Test Point, Compact, Red, TH", Color=Red, Manufacturer=Keystone, PartNumber=5005, Supplier Part Number 1=36-5005-ND
TP59 TP61 TP62 TP63 TP64 TP65 TP66 TP70 TP72 TP73 TP75 TP76 TP78 TP79: library part CMP-0055152-1, "Test Point, Miniature, SMT", Manufacturer=Keystone, Supplier Part Number 1=36-5015TR-ND
U1: library part CMP-0090734-1, "Linear Voltage Regulator IC  1 Output  1A 6-WSON (2x2)", Digikey Part Number=296-TLV76733DRVTCT-ND, Dropout Voltage=0.9V, Manufacturer="Texas Instruments", Max Supply Voltage=16V, Min Supply Voltage=2.5V, Mouser Part Number=595-TLV76733DRVT, Nominal Supply Current=60uA, Operating Temperature Range="-40°C to +125°C", Output Voltage=3.3V
U2: library part CMP-0074206-2, "3-A 17V Step-down Converter Module with Integrated Inductor, SIL0008D (uSIP-8)", Alternate Manufacturer="Texas Instruments", Alternate PartNumber=TPS82130SILT
U3: library part CMP-0079528-1, "TPS53688RSB, RSB0040E (WQFN-40)", Alternate Manufacturer="Texas Instruments"
U4: library part CMP-0054304-1, "High Speed CMOS Logic Quad 2-Input AND Gates, D0014A, TUBE", F @ Nom Voltage(Max)(Mhz)=25, Generic Part Number=CD74HCT08, ICC @ Nom Voltage(Max)(mA)=0.02, Manufacturer="Texas Instruments", Operating Temperature Range(C)="-55 to 125", Rating=Catalog, tpd @ Nom Voltage(Max)(ns)=31, Voltage(Nom)(V)=5
U5 U7: library part CMP-0066944-1, "Dual 4 A Peak High Speed Low-Side Power MOSFET Drivers, D0008A (SOIC-8)", Alternate Manufacturer="Texas Instruments", Alternate PartNumber=UCC27324D
U6: library part CMP-0065673-2, "2.1-MHz, 250-uA, Low-Power Timer, D0008A (SOIC-8)", Alternate Manufacturer="Texas Instruments"
U8 U9 U10 U11 U12 U13 U14 U15: library part CMP-0085794-1, "Synchronous Buck NexFET Smart Power Stage, RWJ0041A (VQFN-CLIP-41)", Alternate Manufacturer="Texas Instruments"
U16: library part CMP-0079627-1, "Configurable Multi-Rail PMIC for 2S & 3S Li-Ion Battery-Operated Devices or Non Battery Operated, RSK0064C (VQFN-64)", Alternate Manufacturer="Texas Instruments", Alternate PartNumber=TPS65086100RSKR
U17: library part CMP-0090775-3, "4.5-V to 18-V Input, Dual 6-A / Single 12-A Output Power Module with Current Sharing", Manufacturer="Texas Instruments", Max Supply Voltage=18V, Min Supply Voltage=4.5V, Nominal Supply Current=2.5mA, Operating Temperature Range="-40°C to +125°C", Output Voltage=0.5-5.5V, Part Number=TPSM5D1806RDBR, Switching Frequency=500-1000-1500-2000kHz
U18 U19: library part CMP-0088389-1, "4.5-V to 18-V Input, Dual 6-A Output Power Module with Current Sharing", Manufacturer="Texas Instruments", Max Supply Voltage=18V, Min Supply Voltage=4.5V, Nominal Supply Current=2500uA, Operating Temperature Range="-40°C to +150°C", Output Voltage=0.5-5.5V, Switching Frequency=500/1000/1500/2250kHz

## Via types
v1: diameter 30, hole 15, Top Layer to Bottom Layer, 1251 vias
v2: diameter 18, hole 8, Top Layer to Bottom Layer, tented both sides, 472 vias
v3: diameter 32, hole 16, Top Layer to Bottom Layer, 464 vias
v4: diameter 30, hole 15, Top Layer to Bottom Layer, tented both sides, 326 vias
v5: diameter 19.68, hole 7.87, Top Layer to Bottom Layer, 323 vias
v6: diameter 26, hole 12, Top Layer to Bottom Layer, tented both sides, 12 vias
v7: diameter 14, hole 6, Top Layer to Bottom Layer, tented both sides, 2 vias
v8: diameter 18, hole 8, Top Layer to Bottom Layer, 1 vias

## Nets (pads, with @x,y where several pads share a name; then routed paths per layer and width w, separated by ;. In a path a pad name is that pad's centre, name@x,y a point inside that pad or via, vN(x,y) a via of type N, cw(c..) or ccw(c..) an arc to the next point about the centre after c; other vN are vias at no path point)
3.3V-Con: C7.1 C9.1 C23.1 C24.1 Q5.2 R5.2 R22.2 R23.2 R30.2 R31.2 R32.2 R34.2 R35.2 R36.2 R130.2 R131.2 R132.2 R133.2 R134.2 R135.2 R136.2 R137.2 R138.2 S3.1 S3.2 S3.3 S3.4 TP6.1 U3.39 | length 1436.6
  Top Layer w6: v4(4142.33,3803) Q5.2@4178.79,3803 ; v4(4238.34,3732.07) 4317.97,3732.07 R136.2@4319.18,3730.86 ; v4(4269.47,3979.13) R135.2@4320.39,3979.13 4321.38,3979.13 4366.7,3933.81 4366.7,3932.47 4382.4,3916.76 R134.2@4383.39,3916.76 ; v4(4269.47,4202.94) 4320.23,4202.94 R133.2@4320.35,4203.06 4321.34,4203.06 4366.66,4157.74 4366.66,4156.05 4382.36,4140.35 R132.2@4383.34,4140.35 ; v4(4269.47,4634.19) R137.2@4319.41,4634.19 4320.39,4634.19 4336.09,4618.49 4336.09,4617.51 4365.73,4587.87 4365.73,4586.06 4381.43,4570.36 R130.2@4382.42,4570.36 4385.96,4573.9 R23.2@4442.9,4573.9 ; v4(4271.28,4426.2) 4320.92,4426.2 R138.2@4321.22,4425.9 ; R138.2@4319.41,4425.6 4320.39,4425.6 4365.71,4380.27 4365.71,4378.8 4381.42,4363.1 R131.2@4382.4,4363.1 4384.9,4365.6 R22.2@4453.15,4365.6 ; R130.2@4365.71,4585.88 4365.71,4579.24 4381.42,4563.54 R130.2@4382.4,4563.54 ; v2(6387.3,4716.1) 6388.25,4715.15 6423.56,4715.15 R35.2@6424.51,4714.2 ; v2(6387.87,4774.11) 6387.87,4775.28 6405.97,4793.38 R34.2@6406.76,4793.38 6406.76,4816.35 6411.06,4820.66 6423.95,4820.66 6426.16,4822.87 6426.16,4859.97 6425.51,4859.97 6409.89,4875.6 6398.41,4875.6 v2(6396.11,4877.89) ; v2(7128.13,4862.6) TP6.1@7128.13,4902.33
  Top Layer w10: U3.39@6704.62,4793.38 6731.83,4793.38 v2(6733.08,4794.63)
  GND5 w6: v2(6387.3,4716.1) v2@6387.58,4716.38 ; v2@6387.58,4773.83 v2(6387.87,4774.11)
  Power 1 w6: v2@6387.58,4716.38 v2@6387.58,4773.83
  Bottom Layer w6: v2(6448.93,4930.11) 6448.93,4933.36 6458.49,4942.92 6458.49,4946.53 6462.73,4950.77 6480,4950.77 R30.2@6508.29,4950.77 R32.2@6540.67,4950.77 ; R36.2@6801.08,4618.97 v2(6832.06,4618.97)
  Bottom Layer w10: v2(6733.08,4794.63) 6735.51,4797.06 6735.89,4797.06 6743.97,4805.14 6758.12,4805.14 6763.12,4810.14 C9.1@6763.12,4812.9 ; C9.1@6762.45,4812.9 6762.45,4893.27 v2(6780.81,4911.64)
  other v2: 7090.29,4862.6 7165.97,4862.6
3V3-LDO: C1.1 R5.1 TP3.1 U1.1 U1.2 | length 70.8
  Top Layer w6: TP3.1@7133.05,4997.2 7167.38,4997.2 7179,5008.82 v2(7179,5028.9)
5V-AUX: C2.1 C3.1 C26.1 C27.2 C30.2 C31.2 R2.2 R84.2 R85.2 U1.4 U1.6 U4.14 U5.6 U6.8 U7.6 | length 1076.2
  Top Layer w15: U7.6@9208.21,1821.64 9208.21,1838.37 9244.1,1874.26 v8(9305.05,1874.26) 9305.62,1873.69 9313.29,1873.69 9365.8,1821.18 C30.2@9365.8,1820.2
  Top Layer w20: v4(2795,1514.4) 2795,1437.93 2804.4,1428.53 U4.14@2804.4,1285.08 ; v4(2986.8,2088.6) 2986.8,2006.66 3097.49,2006.66 3099.16,2004.99 U6.8@3099.16,2004.66 3099.16,2102.37 3079.2,2122.33 R84.2@3079.2,2159.73 ; R85.2@3334.72,1850.32 3335.36,1850.96 3388.56,1850.96 v4(3389.2,1851.6) ; v4(3470.7,1873.63) 3470.99,1873.92 3523.26,1873.92 C27.2@3523.55,1874.21 3589.6,1874.21 3647.04,1816.77 U5.6@3647.04,1800.04
  other v2: 7151.9,5279.8 7183.9,5279.8 7151.9,5308.37 7183.9,5308.23
5V-DRV: C183.1 C200.1 C214.1 C231.1 C246.1 C262.1 C280.1 C296.1 R1.2 R152.1 R159.1 R167.1 R176.1 R183.1 R191.1 R200.1 R207.1 TP2.1 U8.4 U9.4 U10.4 U11.4 U12.4 U13.4 U14.4 U15.4 | length 1712.1
  Top Layer w6: TP2.1@7232.96,5239.78 v2(7232.96,5279.8)
  Top Layer w10: v2(5068.1,4144.5) 5068.1,4100.94 5092.78,4076.26 C183.1@5148.25,4076.26 5169.75,4076.26 5175.02,4081.53 U8.4@5209.67,4081.53 ; v2(5552.41,4129.1) 5552.41,4072.17 5558.27,4066.31 5573.85,4066.31 5576.35,4063.81 5578.74,4066.2 5594.68,4066.2 5610.01,4081.53 U9.4@5630.91,4081.53 ; v2(5969.51,4164.43) 5968.53,4163.45 5968.53,4079.57 5982.4,4065.69 5982.92,4065.69 5986.03,4062.58 6010.43,4062.58 6013.94,4066.1 6013.94,4078.01 6017.46,4081.53 U10.4@6041.07,4081.53 ; v2(6389.17,4155.89) 6366.74,4133.46 6366.74,4074.3 6372.6,4068.44 C231.1@6408.21,4068.44 6408.53,4068.76 6425.69,4068.76 6437.41,4080.48 6454.41,4080.48 U11.4@6455.46,4081.53 ; v2(6787.67,4146.26) 6787.67,4086.2 6805.71,4068.16 6831.6,4068.16 6844.96,4081.53 U12.4@6868.12,4081.53 ; v2(7183.28,4130.35) 7183.28,4061.36 7190.05,4054.6 7228.28,4054.6 7233.32,4059.64 7233.32,4076.49 7238.36,4081.53 U13.4@7258.81,4081.53 ; v2(7645.21,4131.57) 7645.21,4082.63 7665.87,4061.98 7667.72,4061.98 7670.22,4059.48 C280.1@7674.72,4059.48 7675.43,4060.19 7692.05,4060.19 7712.99,4081.13 U14.4@7732.9,4081.13 ; v2(8084.85,4145.2) 8085.25,4144.8 8085.25,4078.17 8105.96,4057.46 C296.1@8125.2,4057.46 8141.86,4057.46 8149.51,4065.11 8149.51,4079.12 8153.03,4082.63 8175.13,4082.63 U15.4@8175.92,4081.84
  Bottom Layer w6: v2(6389.17,4155.89) 6391.46,4153.6 6391.46,4146.69 6403.13,4135.03 R176.1@6407.63,4135.03 ; v2(6787.67,4146.26) 6789.61,4148.21 6812,4148.21 R183.1@6813.95,4150.15
  Bottom Layer w10: R152.1@5068.1,4118.26 v2(5068.1,4144.5) ; v2(5552.41,4129.1) 5551.76,4129.75 5551.76,4143.64 5555.28,4147.15 R159.1@5576.28,4147.15 ; v2(5969.51,4164.43) 5969.51,4162.55 5985.9,4146.16 R167.1@5990.4,4146.16 ; R191.1@7246.84,4132.91 7246.84,4165.06 7255.45,4173.68 v2(7255.45,4176.93) ; v2(7645.21,4131.57) 7645.29,4131.65 7663.21,4131.65 7670.7,4124.17 R200.1@7706.6,4124.17 ; v2(8084.85,4145.2) 8085.4,4145.75 8114.85,4145.75 R207.1@8115.4,4146.3
  other v2: 7265.81,5279.8 7232.96,5308.09 7265.81,5308.09
5V_INT: C5.1 C6.1 R1.1 R2.1 R3.2 TP4.1 U2.4 U2.5 | length 33.6
  Top Layer w6: TP4.1@7210.37,5455.65 7210.52,5455.8 7243.7,5455.8 TP4.1@7243.85,5455.95
5V_MODULE: C359.1 C360.1 C361.1 C362.1 C363.1 C364.1 C365.1 C366.1 C367.1 C368.1 J19.1 J19.3 J33.2 R228.2 TP1.1 U17.13 U17.14 U17.15 U17.16 U17.17 U17.18 U17.19 U17.20 U17.21 U17.22 U17.23 U17.24 U17.25 U17.26 | length 866.6
  Top Layer w6: R228.2@7063,6336.81 v2(7063,6365.54)
  Singal 3 w6: v2(7063,6365.54) 7232.66,6365.54 7245.4,6352.8 7245.4,5911.24 v1(7097.87,5763.71)
  other v1: 6739.74,5708.83 6790.9,5708.83 6842.06,5708.83 6893.22,5708.83 6944.39,5708.83 6995.55,5708.83 7046.71,5708.83 7097.87,5708.83 7149.04,5708.83 6739.74,5763.71 6790.9,5763.71 6842.06,5763.71 7046.71,5763.71 7149.04,5763.71
  other v4: 4175.8,5907.7 4229.3,5907.7 4175.8,5986.2 4229.3,5986.2 4175.8,6064.7 4229.3,6064.7
ACSP1: R151.2 U3.23 | length 109.4
  Top Layer w6: R151.2@6518.95,4566.2 6518.65,4566.5 6518.65,4580.15 6530.9,4592.4 6548.22,4592.4 6570.77,4614.94 U3.23@6570.77,4643.78
ACSP2: R160.2 U3.24 | length 85.1
  Top Layer w6: R160.2@6557.75,4566.1 6562.25,4566.1 6586.51,4590.36 6586.51,4636.13 U3.24@6586.17,4636.47
ACSP3: R168.2 U3.25 | length 79.9
  Top Layer w6: R168.2@6596.75,4566.5 6597.29,4566.5 6601.79,4571 6601.79,4643.3 U3.25@6602.26,4643.78
ACSP4: R175.2 U3.26 | length 87.9
  Top Layer w6: U3.26@6618.01,4643.78 6618.01,4611.19 6635.41,4593.79 6635.41,4569.39 6635.41,4566.87 R175.2@6635.35,4566.8 R175.2@6632.76,4569.39
ACSP5: R184.2 U3.27 | length 103.3
  Top Layer w6: U3.27@6633.76,4643.78 6633.76,4620.44 6673.77,4580.43 6673.77,4568.27 R184.2@6674.05,4568 6669.55,4568 R184.2@6665.05,4572.5
ACSP6: R192.2 U3.28 | length 120
  Top Layer w6: U3.28@6649.51,4643.78 6649.51,4622.96 6680.27,4592.2 6710.63,4592.2 6714.15,4588.69 R192.2@6714.15,4568.3
AGND1: C369.2 NT16.2 R229.2 R231.2 R232.2 U17.42 U17.43 | length 53.4
  Top Layer w6: U17.43@6947.35,6269.66 6947.35,6260.8 6955.21,6252.94 6955.21,6249.02 NT16.2@6957.21,6247.02 6959.21,6249.02 6959.21,6252.98 6967.04,6260.8 U17.42@6967.04,6269.66
AGND2: C382.2 NT17.1 R234.2 R237.2 R238.2 R239.1 U18.39 U18.41 U18.42 U18.43 | length 24.1
  Top Layer w6: NT17.1@6887.3,5310.89 U18.42@6911.43,5310.89
AGND2_U19: C389.2 NT18.1 R241.2 R244.2 R245.2 R246.1 U19.39 U19.41 U19.42 U19.43 | length 48.3
  Top Layer w6: U19.43@7535.79,6269.66 7535.79,6260.8 7537.72,6258.88 7539.11,6258.88 NT18.1@7545.53,6252.47 ; NT18.1@7545.53,6248.47 NT18.1@7545.53,6252.47 ; U19.42@7555.48,6269.66 7555.48,6260.8 7553.56,6258.88 7551.94,6258.88 NT18.1@7545.53,6252.47
APWM1: R150.2 U3.8 | length 132.5
  Top Layer w6: R150.2@6502.99,4926.58 6502.99,4900.53 6525.72,4877.8 6543.77,4877.8 6570.77,4850.8 U3.8@6570.77,4832.75
APWM2: R158.2 U3.7 | length 112
  Top Layer w6: R158.2@6542.56,4926.58 6542.56,4894.57 6586.51,4850.61 U3.7@6586.51,4832.75
APWM3: R166.2 U3.6 | length 102.2
  Top Layer w6: R166.2@6582.12,4926.58 6582.12,4874.76 6602.26,4854.62 U3.6@6602.26,4832.75
APWM4: R174.2 U3.5 | length 102
  Top Layer w6: U3.5@6618.01,4832.75 6618.01,4860.98 6609.99,4869 6609.99,4888.83 6621.69,4900.53 R174.2@6621.69,4926.58
APWM5: R182.2 U3.4 | length 924.9
  Top Layer w6: v2(6626.99,4881.79) 6626.99,4867.56 6633.76,4860.79 U3.4@6633.76,4832.75 ; R182.2@6998.61,4270.49 6998.61,4297.49 7004.91,4303.79 v2(7041.21,4303.79)
  Signal 2 w6: v2(6626.99,4881.79) 6626.99,4863.73 6640.46,4850.26 6727.91,4850.26 6859.88,4718.3 6859.88,4521.78 7041.21,4340.45 v2(7041.21,4303.79)
APWM6: R190.2 U3.3 | length 1207.4
  Top Layer w6: U3.3@6649.51,4832.75 v2(6649.51,4899.24) ; R190.2@7392.92,4270.49 7392.92,4291.04 7396.42,4294.55 v2(7396.42,4297.79)
  Signal 2 w6: v2(6649.51,4899.24) 6649.51,4868.66 6653.86,4864.31 6739.05,4864.31 6882.09,4721.27 6882.09,4682.12 6965.42,4598.79 6965.42,4486.69 7098.5,4353.6 7356.96,4353.6 7394.77,4315.79 7394.77,4299.45 v2(7396.42,4297.79)
ATAO: R27.2 R153.1 R161.1 R169.1 R177.1 R185.1 R193.1 | length 2938.5
  Top Layer w6: v2(5666.54,4294.65) 5697.5,4294.65 5701.02,4291.13 R161.1@5701.02,4265.93 ; v2(6074.53,4302.09) 6074.53,4298.85 6083.28,4290.09 R169.1@6083.28,4267.16 ; R177.1@6492.48,4267.16 6492.48,4281.66 6497.98,4287.16 v2(6497.98,4290.4) ; v2(6923.24,4516.68) 7079.59,4673.03 R27.2@7079.59,4714.52 ; R185.1@6932.22,4270.49 v2(6932.22,4297.19) ; R193.1@7323.11,4270.49 7323.11,4286.93 7329.93,4293.76 v2(7329.93,4295.99)
  Signal 1 w6: v2(5269.71,4284.39) 5302.52,4317.2 5449.62,4317.2 5479.88,4286.93 5657.03,4286.93 5664.74,4294.65 v2(5666.54,4294.65) 5683.7,4311.8 5703.19,4331.3 5798.7,4331.3 5844.91,4285.09 6057.53,4285.09 v2(6074.53,4302.09) 6085.05,4312.62 6475.77,4312.62 v2(6497.98,4290.4) ; v2(6923.24,4516.68) 6923.24,4306.71 6932.22,4297.72 v2(6932.22,4297.19) 6979.23,4344.2 7304.63,4344.2 7329.93,4318.9 v2(7329.93,4295.99)
  Singal 3 w6: v2(6497.98,4290.4) 6533.88,4326.3 6903.12,4326.3 v2(6932.22,4297.19)
  Bottom Layer w6: R153.1@5248.68,4244.65 5248.68,4263.36 v2@5269.5,4284.18
BCSP1: R208.2 U3.30 | length 1691.8
  Top Layer w6: U3.30@6681,4643.78 6702.97,4643.78 v2(6730.45,4616.29) ; R208.2@8147.46,4270.1 8147.46,4309.87 8160.08,4322.49 v2(8160.08,4322.7)
  Power 2 w6: v2(6730.45,4616.29) 6730.45,4600.03 6936.55,4393.93 8110.06,4393.93 8160.08,4343.9 v2(8160.08,4322.7)
BCSP2: R199.2 U3.29 | length 1246.2
  Top Layer w6: U3.29@6665.25,4643.78 6665.25,4627.03 6681.09,4611.19 v2(6696.45,4611.19) ; R199.2@7683.54,4270.1 7683.54,4302.09 7692.4,4310.94 v2(7692.4,4311.6)
  Power 2 w6: v2(6696.45,4611.19) 6696.45,4584.68 6942.14,4338.99 7683.71,4338.99 7692.4,4330.29 v2(7692.4,4311.6)
BIOUT1: J44.2 R208.1 U15.38 | length 2749.9
  Top Layer w6: R208.1@8144.17,4230.44 8147.23,4227.38 8147.23,4217.11 v2(8172.11,4192.24) 8200.38,4192.24 8208.94,4183.67 U15.38@8208.94,4158.89
  Power 3 w6: v2(8172.11,4192.24) 8221.54,4241.67 9356.93,4241.67 9493.5,4105.1 10570.4,4105.1 10582.2,4116.9 10582.2,4146.1 10599.85,4163.75 10629.05,4163.75 J44.2@10671.2,4205.9
BIOUT2: J43.2 R199.1 U14.38 | length 3275.8
  Top Layer w6: R199.1@7691.95,4230.1 7691.95,4213.6 7698.42,4207.13 7704.3,4207.13 v2(7706.6,4204.83) 7723.53,4187.9 7759.6,4187.9 7766.36,4181.14 U14.38@7766.36,4158.89
  Signal 1 w6: v2(7706.6,4204.83) 7753.73,4204.83 7791.7,4242.8 9860.2,4242.8 9982.9,4120.1 10345.3,4120.1 10579.6,4354.4 10620.5,4354.4 J43.2@10671.2,4405.1
BOOT1: C308.1 U16.35 | length 48.2
  Top Layer w6: C308.1@5835.18,5532.63 U16.35@5835.18,5580.87
BOOT2: C318.1 U16.5 | length 79.4
  Top Layer w6: U16.5@5976.91,5884.02 C318.1@5976.91,5963.43
BOOT6: C300.1 U16.41 | length 51
  Top Layer w6: C300.1@5929.66,5529.9 U16.41@5929.66,5580.87
BP5-3: C369.1 U17.44 | length 62.4
  Top Layer w6: C369.1@6907.24,6323.56 6907.24,6307.2 6927.08,6287.35 6927.08,6270.24 U17.44@6927.67,6269.66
